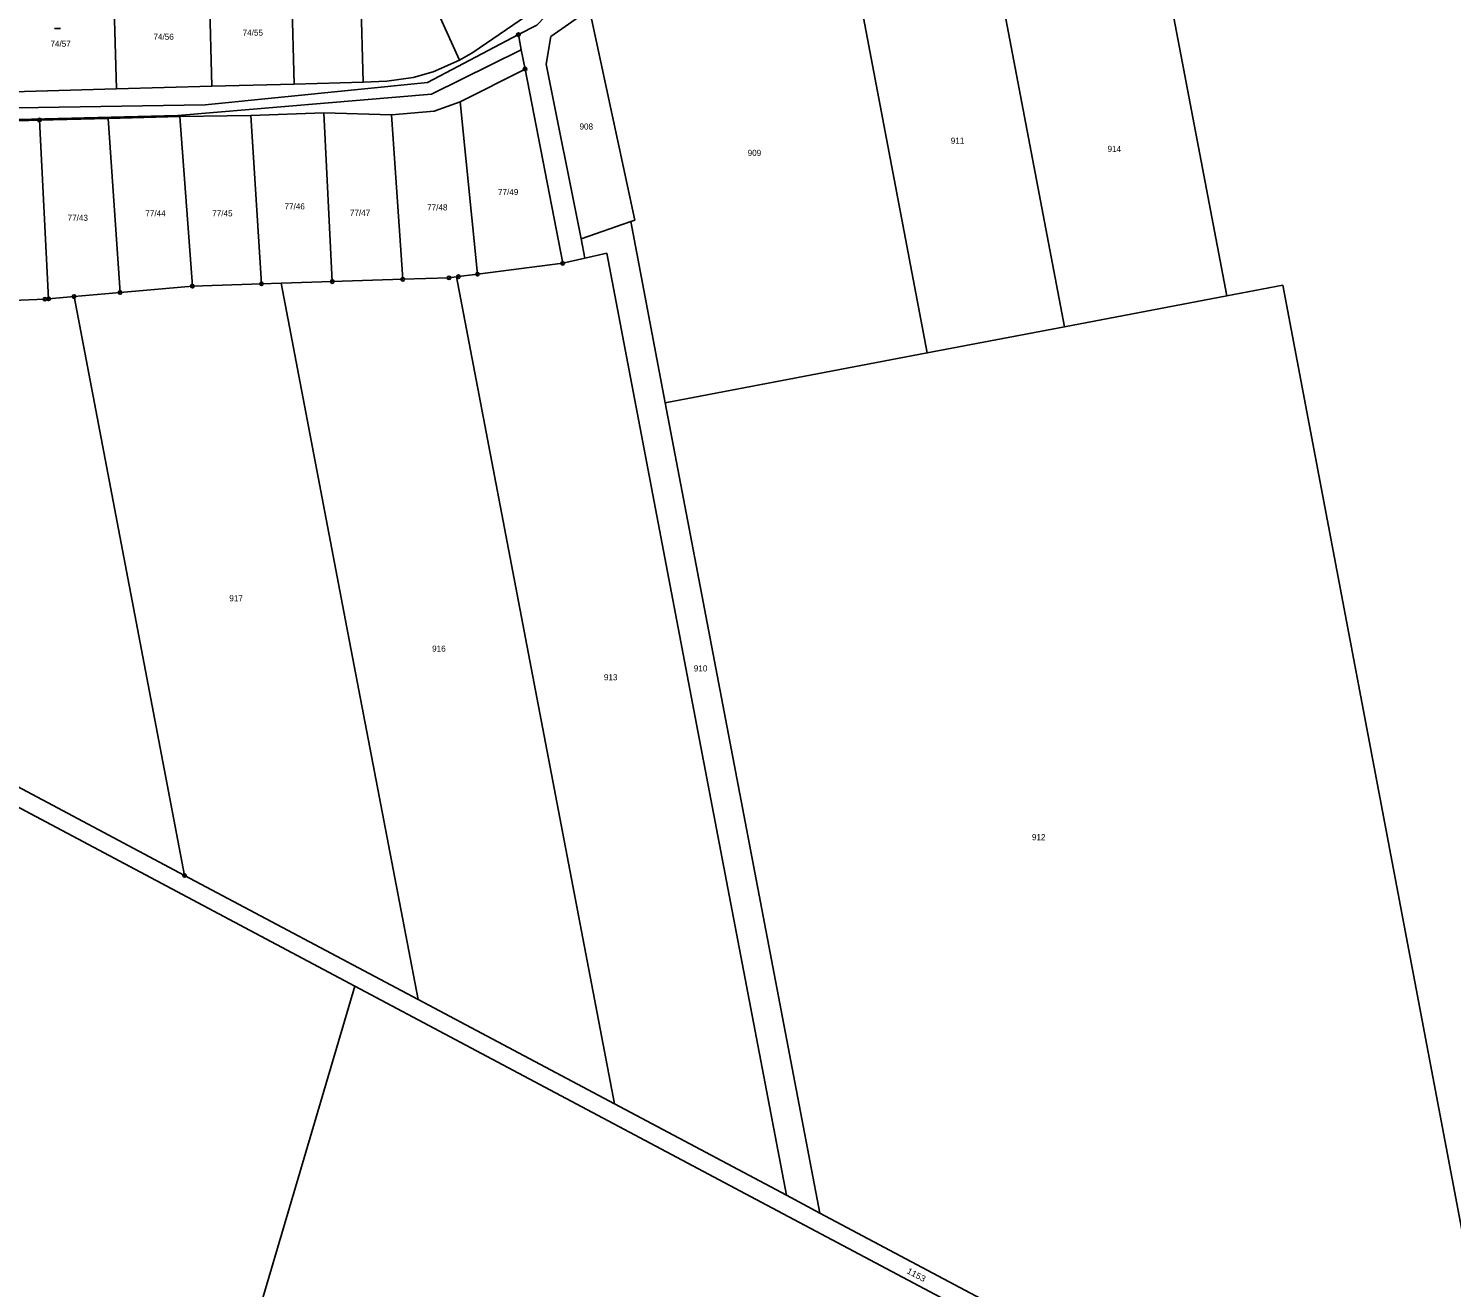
# Model space of a CAD drawing. Extents: x -758887 to -754328, y -1031688 to -1029144.
# Drawn here: x -756420.8 to -756022.6, y -1031001.8 to -1030649.6 of the extents above; entities that cross this region are included whole.
import ezdxf
from ezdxf.enums import TextEntityAlignment as Align

# ---------------------------------------------------------------- set-up
doc = ezdxf.new("R2010")
doc.units = 0
doc.header["$LTSCALE"] = 0.68
for name, color, linetype, lineweight in [('1', 7, 'Continuous', 25), ('3', 7, 'Continuous', 25), ('8', 7, 'Continuous', 25)]:
    doc.layers.add(name, color=color, linetype=linetype, lineweight=lineweight)
doc.layers.add('2', color=7, linetype='Continuous')

msp = doc.modelspace()

# ---------------------------------------------------------------- linework, layer by layer
at = {"layer": '1'}
for p, q in [((-756328.56, -1030613.48), (-756327.16, -1030664.64)), ((-756347.65, -1030621.07), (-756346.44, -1030665.17)), ((-756370.44, -1030630.13), (-756369.47, -1030665.8)), ((-756397.1, -1030633.48), (-756396.2, -1030666.53)), ((-756312.2, -1030631.86), (-756300.24, -1030658.53)), ((-756085.48, -1030724.4), (-756102.87, -1030633.12)), ((-756282.9, -1030655.55), (-756283.71, -1030651.34)), ((-756281.85, -1030660.98), (-756282.9, -1030655.55)), ((-756299.97, -1030670.12), (-756281.85, -1030660.98)), ((-756281.85, -1030660.98), (-756271.33, -1030715.31)), ((-756295.16, -1030718.35), (-756299.97, -1030670.12)), ((-756374.95, -1030721.68), (-756378.46, -1030674.21)), ((-756355.61, -1030721.06), (-756358.59, -1030673.95)), ((-756335.79, -1030720.42), (-756338.15, -1030673.21)), ((-756316.08, -1030719.79), (-756319.23, -1030673.82)), ((-756415.17, -1030725.25), (-756417.72, -1030675.24)), ((-756395.19, -1030723.48), (-756398.55, -1030674.79)), ((-756266.16, -1030708.47), (-756252.3, -1030703.63)), ((-756266.16, -1030708.47), (-756265.09, -1030713.88)), ((-756265.09, -1030713.88), (-756271.33, -1030715.31)), ((-756271.33, -1030715.31), (-756295.16, -1030718.35)), ((-756355.61, -1030721.06), (-756374.95, -1030721.68)), ((-756350.08, -1030720.88), (-756355.61, -1030721.06)), ((-756335.79, -1030720.42), (-756350.08, -1030720.88)), ((-756316.08, -1030719.79), (-756335.79, -1030720.42)), ((-756408.07, -1030724.62), (-756415.17, -1030725.25)), ((-756408.07, -1030724.62), (-756377.14, -1030886.55)), ((-756468.07, -1030838.25), (-756377.14, -1030886.55)), ((-756377.14, -1030886.55), (-756311.81, -1030921.25)), ((-756311.81, -1030921.25), (-756256.84, -1030950.44))]:
    msp.add_line(p, q, dxfattribs=at)
for points in [[(-756252.3, -1030703.63), (-756242.62, -1030754.34), (-756169.3, -1030740.37), (-756192.51, -1030618.56)], [(-756169.3, -1030740.37), (-756130.93, -1030733.06), (-756151.84, -1030623.3)], [(-756276.53, -1030642.74), (-756279.65, -1030644.86), (-756296.45, -1030656.34), (-756300.24, -1030658.53)], [(-756283.71, -1030651.34), (-756278.6, -1030648.65), (-756276.19, -1030646.26)], [(-756263.78, -1030644.29), (-756274.62, -1030651.91), (-756275.93, -1030659.65), (-756266.16, -1030708.47)], [(-756252.3, -1030703.63), (-756251.14, -1030703.23), (-756263.78, -1030644.29)], [(-756493.95, -1030672.9), (-756371.38, -1030670.94), (-756309.15, -1030664.75), (-756283.71, -1030651.34)], [(-756282.9, -1030655.55), (-756308.06, -1030668.02), (-756379, -1030674.01), (-756490.83, -1030676.79), (-756512.76, -1030685.59), (-756531.71, -1030701.08), (-756573.47, -1030723.47), (-756585.94, -1030732.18), (-756597.17, -1030744.56)], [(-756300.24, -1030658.53), (-756307.58, -1030661.72), (-756313.13, -1030663.29), (-756320.52, -1030664.4), (-756327.16, -1030664.64), (-756346.44, -1030665.17), (-756369.47, -1030665.8), (-756396.2, -1030666.53), (-756425.23, -1030667.33), (-756457.25, -1030668.21)], [(-756319.23, -1030673.82), (-756307.25, -1030672.71), (-756299.97, -1030670.12)], [(-756552.63, -1030716.6), (-756528.83, -1030700.94), (-756520.58, -1030695.27), (-756513.09, -1030690.29), (-756504.73, -1030685.58), (-756492.87, -1030681.04), (-756481.59, -1030678.54), (-756464.91, -1030676.57), (-756446.91, -1030676.02), (-756435.73, -1030675.84), (-756417.72, -1030675.24), (-756398.55, -1030674.79), (-756378.46, -1030674.21), (-756358.59, -1030673.95), (-756338.15, -1030673.21), (-756319.23, -1030673.82)], [(-756265.09, -1030713.88), (-756259.01, -1030712.49), (-756233.85, -1030844.25), (-756208.69, -1030976.01), (-756199.33, -1030980.98)], [(-756295.16, -1030718.35), (-756300.49, -1030719.03), (-756301.02, -1030719.1)], [(-756374.95, -1030721.68), (-756395.19, -1030723.48), (-756408.07, -1030724.62)], [(-756350.08, -1030720.88), (-756330.95, -1030821.07), (-756311.81, -1030921.25)], [(-756301.02, -1030719.1), (-756303.16, -1030719.37), (-756316.08, -1030719.79)], [(-756301.02, -1030719.1), (-756278.93, -1030834.77), (-756256.84, -1030950.44), (-756208.69, -1030976.01)], [(-756000.57, -1031086.55), (-756035.21, -1030904.01), (-756069.85, -1030721.46), (-756085.48, -1030724.4), (-756130.93, -1030733.06)], [(-756415.17, -1030725.25), (-756416.23, -1030725.34), (-756434.41, -1030726.09), (-756444.38, -1030726.5)], [(-756199.33, -1030980.98), (-756220.98, -1030867.66), (-756242.62, -1030754.34)], [(-756441.29, -1031306.34), (-756406.04, -1031176.45), (-756367.75, -1031046.99), (-756329.46, -1030917.53), (-756436.41, -1030860.73)], [(-756104.92, -1031036.79), (-756217.19, -1030977.16), (-756329.46, -1030917.53)], [(-756199.33, -1030980.98), (-756099.95, -1031033.77), (-756000.57, -1031086.55)]]:
    msp.add_lwpolyline(points, dxfattribs=at)
at = {"layer": '3'}
msp.add_line((-756413.553, -1030649.62), (-756411.803, -1030649.62), dxfattribs=at)
at = {"layer": '8'}
for centre, radius in [((-756283.71, -1030651.3399), 0.5), ((-756283.71, -1030651.3399), 0.0303), ((-756281.85, -1030660.9799), 0.5), ((-756281.85, -1030660.9799), 0.0303), ((-756417.72, -1030675.2399), 0.5), ((-756417.72, -1030675.2399), 0.0303), ((-756295.16, -1030718.3499), 0.5), ((-756295.16, -1030718.3499), 0.0303), ((-756271.33, -1030715.3099), 0.5), ((-756271.33, -1030715.3099), 0.0303), ((-756374.95, -1030721.6799), 0.5), ((-756374.95, -1030721.6799), 0.0303), ((-756355.61, -1030721.0599), 0.5), ((-756355.61, -1030721.0599), 0.0303), ((-756335.79, -1030720.4199), 0.5), ((-756335.79, -1030720.4199), 0.0303), ((-756316.08, -1030719.7899), 0.5), ((-756316.08, -1030719.7899), 0.0303), ((-756303.16, -1030719.3699), 0.5), ((-756303.16, -1030719.3699), 0.0303), ((-756300.49, -1030719.0299), 0.5), ((-756300.49, -1030719.0299), 0.0303), ((-756416.23, -1030725.3399), 0.5), ((-756416.23, -1030725.3399), 0.0303), ((-756415.17, -1030725.2499), 0.5), ((-756415.17, -1030725.2499), 0.0303), ((-756408.07, -1030724.6199), 0.5), ((-756408.07, -1030724.6199), 0.0303), ((-756395.19, -1030723.4799), 0.5), ((-756395.19, -1030723.4799), 0.0303), ((-756377.14, -1030886.5499), 0.5), ((-756377.14, -1030886.5499), 0.0303)]:
    msp.add_circle(centre, radius, dxfattribs=at)

# ---------------------------------------------------------------- texts
at = {"layer": '2'}
for s, p in [('74/55', (-756358.03, -1030651.63)), ('74/57', (-756411.82, -1030654.73)), ('74/56', (-756382.99, -1030652.79)), ('908', (-756264.719, -1030677.896)), ('911', (-756160.839, -1030681.866)), ('914', (-756116.969, -1030684.156)), ('909', (-756217.679, -1030685.266)), ('917', (-756362.709, -1030809.856)), ('916', (-756305.969, -1030823.946)), ('910', (-756232.739, -1030829.486)), ('913', (-756257.889, -1030831.946)), ('912', (-756138.129, -1030876.686))]:
    msp.add_text(s, height=1.7, dxfattribs=at).set_placement(p, align=Align.CENTER)
for s, p in [('77/49', (-756289.43, -1030696.22)), ('77/46', (-756349.16, -1030700.24)), ('77/43', (-756409.86, -1030703.43)), ('77/44', (-756388.1, -1030702.18)), ('77/45', (-756369.39, -1030702.18)), ('77/47', (-756330.87, -1030702.04)), ('77/48', (-756309.25, -1030700.52))]:
    msp.add_text(s, height=1.7, dxfattribs=at).set_placement(p)
at = {"layer": '2', "width": 1.1}
msp.add_text('1153', height=1.7, rotation=332, dxfattribs=at).set_placement((-756172.7581, -1030999.0116), align=Align.CENTER)

doc.saveas('drawing.dxf')
